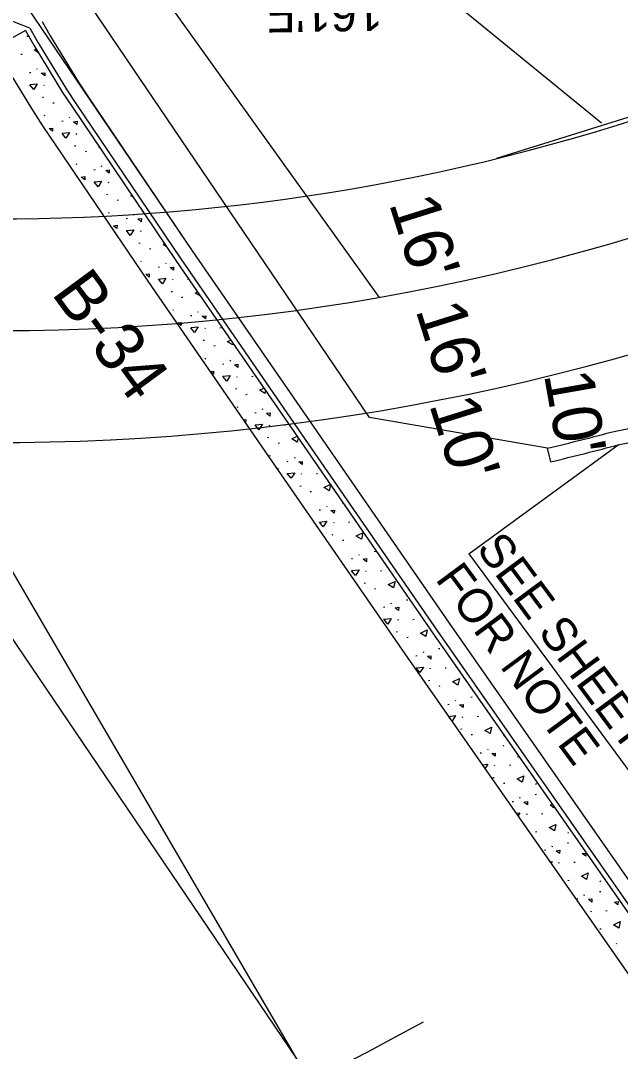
# Model space of a CAD drawing. Extents: x 1966090 to 1975830, y 788086 to 801233.
# Drawn here: x 1971355.4 to 1971441.1, y 796145.9 to 796293.3 of the extents above; entities that cross this region are included whole.
import ezdxf

# ---------------------------------------------------------------- set-up
doc = ezdxf.new("R2010")
doc.units = 0
for name, color, linetype in [('BR_PRESTRESSED BEAM', 7, 'Continuous'), ('BR_PROPOSED_DRAINAGE', 7, 'Continuous'), ('BR_REBAR', 7, 'Continuous'), ('BR_SITE LOCATION', 7, 'Continuous'), ('RD_EX_Driveway_txCode', 7, 'Continuous'), ('RD_EX_RW_TX', 7, 'Continuous'), ('RD_EX_SU_Gas', 7, 'Continuous'), ('RD_EX_TX_Dam_ELEV', 7, 'Continuous'), ('RD_PD_PaveShd', 7, 'Continuous'), ('RD_PD_RW_TX', 7, 'Continuous'), ('RD_Sketch6', 7, 'Continuous'), ('RD_Sketch8', 7, 'Continuous')]:
    doc.layers.add(name, color=color, linetype=linetype)

msp = doc.modelspace()

# ---------------------------------------------------------------- linework, layer by layer
at = {"layer": 'BR_PRESTRESSED BEAM'}
msp.add_line((1971458.75, 796284.65), (1971423.44, 796273.61), dxfattribs=at)
at = {"layer": 'BR_PROPOSED_DRAINAGE'}
msp.add_line((1971321.61, 796270.35), (1971480.17, 795998.61), dxfattribs=at)
msp.add_lwpolyline([(1971355.49, 796296.53), (1971379.93, 796260.39), (1971397.2, 796235.33), (1971416.64, 796207.13), (1971494.67, 796095.38), (1971512.27, 796070.43)], dxfattribs=at)
at = {"layer": 'BR_REBAR'}
for p, q in [((1971440.43, 796234.62), (1971528.98, 796252.31)), ((1971440.82, 796232.66), (1971518, 796248.07)), ((1971431.2, 796230.22), (1971430.74, 796232.16))]:
    msp.add_line(p, q, dxfattribs=at)
for points in [[(1971358.49, 796293.18), (1971359.61, 796291.14), (1971363.68, 796284.48), (1971364.94, 796282.55), (1971379.93, 796260.39), (1971397.2, 796235.33), (1971416.64, 796207.13), (1971494.67, 796095.38), (1971512.27, 796070.43)], [(1971356.73, 796292.22), (1971357.88, 796290.13), (1971361.99, 796283.41), (1971363.28, 796281.44), (1971378.28, 796259.26), (1971395.55, 796234.19), (1971414.99, 796205.99), (1971493.03, 796094.24), (1971510.62, 796069.31)]]:
    msp.add_lwpolyline(points, dxfattribs=at)
for radius in [340, 342]:
    msp.add_arc((1971352.19, 796562.97), radius, 283.357, 285.0421, dxfattribs=at)
at = {"layer": 'BR_SITE LOCATION'}
for p, q in [((1971356.11, 796291.89), (1971351.73, 796289.49)), ((1971356.27, 796291.07), (1971356.45, 796291.1)), ((1971355.41, 796288.49), (1971355.59, 796288.52)), ((1971357.35, 796289.09), (1971357.61, 796289.22)), ((1971357.89, 796288.76), (1971357.36, 796289.08)), ((1971356.68, 796285.87), (1971356.86, 796285.9)), ((1971357.77, 796286.42), (1971357.72, 796286.3)), ((1971358.76, 796284.08), (1971358.7, 796283.96)), ((1971358.5, 796282.34), (1971358.68, 796282.37)), ((1971360.01, 796281.54), (1971360.19, 796281.57)), ((1971361.95, 796282.14), (1971361.97, 796282.15)), ((1971361.99, 796282.12), (1971361.96, 796282.13)), ((1971358.79, 796279.76), (1971358.74, 796279.63)), ((1971362.37, 796279.47), (1971362.32, 796279.35)), ((1971361.28, 796278.92), (1971361.46, 796278.95)), ((1971363.36, 796277.14), (1971363.3, 796277.01)), ((1971363.1, 796275.39), (1971363.28, 796275.42)), ((1971366.55, 796275.2), (1971366.63, 796275.23)), ((1971366.72, 796275.09), (1971366.57, 796275.18)), ((1971364.61, 796274.59), (1971364.79, 796274.62)), ((1971363.39, 796272.81), (1971363.34, 796272.69)), ((1971365.88, 796271.97), (1971366.06, 796272)), ((1971366.97, 796272.53), (1971366.92, 796272.4)), ((1971367.96, 796270.19), (1971367.9, 796270.07)), ((1971367.7, 796268.44), (1971367.88, 796268.47)), ((1971369.21, 796267.64), (1971369.39, 796267.67)), ((1971371.15, 796268.25), (1971371.3, 796268.32)), ((1971371.49, 796268.04), (1971371.17, 796268.24)), ((1971367.99, 796265.86), (1971367.94, 796265.74)), ((1971370.48, 796265.02), (1971370.66, 796265.05)), ((1971371.57, 796265.58), (1971371.52, 796265.45)), ((1971372.56, 796263.24), (1971372.51, 796263.12)), ((1971374.67, 796263.28), (1971374.7, 796263.29)), ((1971372.3, 796261.49), (1971372.48, 796261.52)), ((1971373.81, 796260.69), (1971373.99, 796260.72)), ((1971375.75, 796261.3), (1971375.97, 796261.41)), ((1971376.26, 796260.98), (1971375.77, 796261.29)), ((1971372.59, 796258.91), (1971372.54, 796258.79)), ((1971375.08, 796258.07), (1971375.26, 796258.1)), ((1971376.17, 796258.63), (1971376.12, 796258.51)), ((1971377.16, 796256.29), (1971377.11, 796256.17)), ((1971379.27, 796256.33), (1971379.42, 796256.36)), ((1971376.91, 796254.55), (1971377.09, 796254.58)), ((1971380.35, 796254.35), (1971380.69, 796254.51)), ((1971378.41, 796253.74), (1971378.59, 796253.77)), ((1971377.2, 796251.96), (1971377.14, 796251.84)), ((1971380.77, 796251.68), (1971380.72, 796251.56)), ((1971379.68, 796251.12), (1971379.86, 796251.15)), ((1971381.76, 796249.34), (1971381.71, 796249.22)), ((1971383.87, 796249.38), (1971384.05, 796249.41)), ((1971381.51, 796247.6), (1971381.69, 796247.63)), ((1971384.95, 796247.4), (1971385.43, 796247.63)), ((1971383.01, 796246.8), (1971383.19, 796246.83)), ((1971381.8, 796245.02), (1971381.74, 796244.89)), ((1971384.28, 796244.18), (1971384.46, 796244.21)), ((1971385.38, 796244.73), (1971385.32, 796244.61)), ((1971386.36, 796242.39), (1971386.31, 796242.27)), ((1971388.47, 796242.44), (1971388.65, 796242.47)), ((1971386.11, 796240.65), (1971386.29, 796240.68)), ((1971387.61, 796239.85), (1971387.79, 796239.88)), ((1971389.55, 796240.45), (1971390.18, 796240.75)), ((1971386.4, 796238.07), (1971386.34, 796237.94)), ((1971388.88, 796237.23), (1971389.06, 796237.26)), ((1971389.98, 796237.78), (1971389.92, 796237.66)), ((1971390.96, 796235.45), (1971390.91, 796235.32)), ((1971393.07, 796235.49), (1971393.25, 796235.52)), ((1971390.71, 796233.7), (1971390.89, 796233.73)), ((1971394.15, 796233.51), (1971394.92, 796233.87)), ((1971392.21, 796232.9), (1971392.39, 796232.93)), ((1971391, 796231.12), (1971390.95, 796231)), ((1971394.58, 796230.84), (1971394.53, 796230.71)), ((1971393.48, 796230.28), (1971393.66, 796230.31)), ((1971395.56, 796228.5), (1971395.51, 796228.38)), ((1971397.67, 796228.54), (1971397.85, 796228.57)), ((1971395.31, 796226.75), (1971395.49, 796226.78)), ((1971398.76, 796226.56), (1971399.66, 796226.99)), ((1971396.81, 796225.95), (1971396.99, 796225.98)), ((1971395.6, 796224.17), (1971395.57, 796224.11)), ((1971398.08, 796223.33), (1971398.26, 796223.36)), ((1971399.18, 796223.89), (1971399.13, 796223.76)), ((1971401.35, 796224.35), (1971401.46, 796224.37)), ((1971400.16, 796221.55), (1971400.11, 796221.43)), ((1971402.27, 796221.59), (1971402.45, 796221.62)), ((1971399.91, 796219.8), (1971400.09, 796219.83)), ((1971401.41, 796219), (1971401.59, 796219.03)), ((1971405.95, 796217.41), (1971406.13, 796217.44)), ((1971402.68, 796216.38), (1971402.86, 796216.41)), ((1971403.78, 796216.94), (1971403.73, 796216.82)), ((1971404.76, 796214.6), (1971404.71, 796214.48)), ((1971406.87, 796214.64), (1971407.05, 796214.67)), ((1971404.51, 796212.86), (1971404.69, 796212.89)), ((1971406.01, 796212.05), (1971406.19, 796212.08)), ((1971410.55, 796210.46), (1971410.73, 796210.49)), ((1971407.28, 796209.44), (1971407.46, 796209.47)), ((1971408.38, 796209.99), (1971408.33, 796209.87)), ((1971409.36, 796207.65), (1971409.31, 796207.53)), ((1971411.47, 796207.69), (1971411.65, 796207.72)), ((1971409.11, 796205.91), (1971409.29, 796205.94)), ((1971410.61, 796205.11), (1971410.79, 796205.14)), ((1971412.98, 796203.04), (1971412.93, 796202.92)), ((1971415.15, 796203.51), (1971415.33, 796203.54)), ((1971411.89, 796202.49), (1971412.07, 796202.52)), ((1971413.96, 796200.71), (1971413.91, 796200.58)), ((1971416.07, 796200.75), (1971416.25, 796200.78)), ((1971413.71, 796198.96), (1971413.89, 796198.99)), ((1971415.21, 796198.16), (1971415.39, 796198.19)), ((1971416.49, 796195.54), (1971416.67, 796195.57)), ((1971417.58, 796196.09), (1971417.53, 796195.97)), ((1971419.76, 796196.56), (1971419.93, 796196.59)), ((1971418.56, 796193.76), (1971418.51, 796193.63)), ((1971420.68, 796193.8), (1971420.85, 796193.83)), ((1971418.31, 796192.01), (1971418.49, 796192.04)), ((1971419.82, 796191.21), (1971420, 796191.24)), ((1971424.52, 796191.11), (1971424.41, 796191.01)), ((1971424.36, 796189.61), (1971424.54, 796189.64)), ((1971421.09, 796188.59), (1971421.27, 796188.62)), ((1971422.18, 796189.15), (1971422.13, 796189.02)), ((1971426.5, 796188.1), (1971426.61, 796188.12)), ((1971426.79, 796187.87), (1971426.5, 796188.1)), ((1971423.16, 796186.81), (1971423.11, 796186.69)), ((1971425.28, 796186.85), (1971425.46, 796186.88)), ((1971422.91, 796185.06), (1971423.09, 796185.09)), ((1971424.42, 796184.26), (1971424.6, 796184.29)), ((1971429.14, 796184.17), (1971429.01, 796184.06)), ((1971426.78, 796182.2), (1971426.73, 796182.07)), ((1971428.96, 796182.66), (1971429.14, 796182.7)), ((1971425.69, 796181.64), (1971425.87, 796181.67)), ((1971431.1, 796181.15), (1971431.44, 796181.2)), ((1971427.76, 796179.86), (1971427.71, 796179.74)), ((1971429.88, 796179.9), (1971430.06, 796179.93)), ((1971427.51, 796178.11), (1971427.69, 796178.14)), ((1971429.02, 796177.31), (1971429.2, 796177.34)), ((1971433.74, 796177.22), (1971433.61, 796177.11)), ((1971430.29, 796174.69), (1971430.47, 796174.72)), ((1971431.38, 796175.25), (1971431.33, 796175.13)), ((1971433.56, 796175.72), (1971433.74, 796175.75)), ((1971432.36, 796172.91), (1971432.31, 796172.79)), ((1971434.48, 796172.95), (1971434.66, 796172.98)), ((1971433.62, 796170.36), (1971433.8, 796170.4)), ((1971438.34, 796170.27), (1971438.21, 796170.16)), ((1971438.16, 796168.77), (1971438.34, 796168.8)), ((1971434.89, 796167.75), (1971435.07, 796167.78)), ((1971435.98, 796168.3), (1971435.93, 796168.18)), ((1971436.97, 796165.96), (1971436.91, 796165.84)), ((1971439.08, 796166.01), (1971439.26, 796166.04)), ((1971438.22, 796163.42), (1971438.4, 796163.45)), ((1971439.58, 796160.81), (1971439.67, 796160.83)), ((1971440.58, 796161.35), (1971440.53, 796161.23))]:
    msp.add_line(p, q, dxfattribs=at)
for points in [[(1971356.11, 796291.89), (1971357.26, 796289.78), (1971361.39, 796283.03), (1971362.69, 796281.05), (1971377.69, 796258.87), (1971394.97, 796233.79), (1971414.41, 796205.59), (1971492.45, 796093.83), (1971517.1, 796058.89)], [(1971351.73, 796289.49), (1971352.93, 796287.27), (1971357.17, 796280.35), (1971358.53, 796278.28), (1971373.56, 796256.05), (1971390.85, 796230.96), (1971410.3, 796202.74), (1971488.36, 796090.96), (1971513.02, 796056.01)], [(1971358.35, 796285.79), (1971358.86, 796285.86), (1971358.83, 796285.39), (1971358.35, 796285.79)], [(1971356.71, 796284.15), (1971357.77, 796284.25), (1971357.26, 796283.45), (1971356.72, 796284.13)], [(1971359.46, 796277.87), (1971359.97, 796277.94), (1971359.94, 796277.48), (1971359.46, 796277.87)], [(1971362.95, 796278.84), (1971363.46, 796278.91), (1971363.43, 796278.45), (1971362.95, 796278.84)], [(1971361.31, 796277.2), (1971362.37, 796277.3), (1971361.86, 796276.5), (1971361.32, 796277.18)], [(1971364.06, 796270.92), (1971364.57, 796270.99), (1971364.55, 796270.53), (1971364.06, 796270.92)], [(1971367.55, 796271.89), (1971368.06, 796271.96), (1971368.03, 796271.5), (1971367.55, 796271.89)], [(1971365.91, 796270.25), (1971366.97, 796270.35), (1971366.46, 796269.55), (1971365.92, 796270.23)], [(1971372.15, 796264.94), (1971372.66, 796265.01), (1971372.63, 796264.55), (1971372.15, 796264.94)], [(1971368.67, 796263.98), (1971369.17, 796264.05), (1971369.15, 796263.58), (1971368.67, 796263.98)], [(1971370.51, 796263.3), (1971371.57, 796263.41), (1971371.06, 796262.6), (1971370.52, 796263.29)], [(1971376.75, 796257.99), (1971377.26, 796258.06), (1971377.23, 796257.6), (1971376.75, 796257.99)], [(1971373.27, 796257.03), (1971373.77, 796257.1), (1971373.75, 796256.64), (1971373.27, 796257.03)], [(1971375.11, 796256.35), (1971376.17, 796256.46), (1971375.66, 796255.65), (1971375.12, 796256.34)], [(1971381.11, 796253.9), (1971381.11, 796253.88), (1971380.37, 796254.34)], [(1971377.87, 796250.08), (1971378.37, 796250.15), (1971378.35, 796249.69), (1971377.87, 796250.08)], [(1971381.35, 796251.04), (1971381.86, 796251.11), (1971381.83, 796250.65), (1971381.35, 796251.04)], [(1971379.71, 796249.4), (1971380.77, 796249.51), (1971380.26, 796248.7), (1971379.72, 796249.39)], [(1971385.76, 796247.16), (1971385.71, 796246.93), (1971384.97, 796247.39)], [(1971385.95, 796244.1), (1971386.46, 796244.17), (1971386.43, 796243.7), (1971385.95, 796244.1)], [(1971382.47, 796243.13), (1971382.98, 796243.2), (1971382.95, 796242.74), (1971382.47, 796243.13)], [(1971384.31, 796242.46), (1971385.37, 796242.56), (1971384.86, 796241.76), (1971384.32, 796242.44)], [(1971390.41, 796240.42), (1971390.31, 796239.99), (1971389.57, 796240.44)], [(1971390.55, 796237.15), (1971391.06, 796237.22), (1971391.03, 796236.76), (1971390.55, 796237.15)], [(1971387.24, 796236.21), (1971387.58, 796236.25), (1971387.55, 796235.79), (1971387.49, 796235.84)], [(1971388.91, 796235.51), (1971389.97, 796235.61), (1971389.46, 796234.81), (1971388.92, 796235.49)], [(1971395.05, 796233.68), (1971394.91, 796233.04), (1971394.17, 796233.49)], [(1971392.01, 796229.28), (1971392.18, 796229.3), (1971392.16, 796229.06)], [(1971395.15, 796230.2), (1971395.66, 796230.27), (1971395.63, 796229.81), (1971395.15, 796230.2)], [(1971393.51, 796228.56), (1971394.58, 796228.66), (1971394.06, 796227.86), (1971393.52, 796228.54)], [(1971399.7, 796226.93), (1971399.51, 796226.09), (1971398.77, 796226.55)], [(1971399.75, 796223.25), (1971400.26, 796223.32), (1971400.23, 796222.86), (1971399.75, 796223.25)], [(1971398.11, 796221.61), (1971399.18, 796221.72), (1971398.67, 796220.91), (1971398.12, 796221.6)], [(1971403.36, 796219.61), (1971404.32, 796220.07), (1971404.11, 796219.14), (1971403.37, 796219.6)], [(1971404.35, 796216.3), (1971404.86, 796216.37), (1971404.84, 796215.91), (1971404.35, 796216.3)], [(1971402.71, 796214.66), (1971403.78, 796214.77), (1971403.27, 796213.96), (1971402.72, 796214.65)], [(1971407.96, 796212.66), (1971408.92, 796213.12), (1971408.71, 796212.19), (1971407.97, 796212.65)], [(1971408.95, 796209.35), (1971409.46, 796209.43), (1971409.44, 796208.96), (1971408.95, 796209.35)], [(1971407.31, 796207.71), (1971408.38, 796207.82), (1971407.87, 796207.01), (1971407.32, 796207.7)], [(1971412.56, 796205.71), (1971413.52, 796206.17), (1971413.31, 796205.24), (1971412.57, 796205.7)], [(1971413.56, 796202.41), (1971414.06, 796202.48), (1971414.04, 796202.02), (1971413.56, 796202.41)], [(1971411.92, 796200.77), (1971412.98, 796200.87), (1971412.47, 796200.07), (1971411.93, 796200.75)], [(1971417.16, 796198.76), (1971418.12, 796199.23), (1971417.92, 796198.3), (1971417.17, 796198.75)], [(1971418.16, 796195.46), (1971418.66, 796195.53), (1971418.64, 796195.07), (1971418.16, 796195.46)], [(1971416.53, 796193.82), (1971417.58, 796193.92), (1971417.07, 796193.12), (1971416.68, 796193.61)], [(1971421.76, 796191.82), (1971422.72, 796192.28), (1971422.52, 796191.35), (1971421.77, 796191.8)], [(1971422.76, 796188.51), (1971423.26, 796188.58), (1971423.24, 796188.12), (1971422.76, 796188.51)], [(1971421.37, 796186.89), (1971422.18, 796186.97), (1971421.77, 796186.32)], [(1971426.36, 796184.87), (1971427.32, 796185.33), (1971427.12, 796184.4), (1971426.37, 796184.86)], [(1971427.36, 796181.56), (1971427.87, 796181.63), (1971427.84, 796181.17), (1971427.36, 796181.56)], [(1971431.6, 796180.98), (1971431.58, 796180.76), (1971431.1, 796181.15)], [(1971426.2, 796179.97), (1971426.78, 796180.03), (1971426.49, 796179.56)], [(1971430.96, 796177.92), (1971431.92, 796178.38), (1971431.72, 796177.45), (1971430.97, 796177.91)], [(1971431.96, 796174.61), (1971432.47, 796174.68), (1971432.44, 796174.22), (1971431.96, 796174.61)], [(1971435.7, 796174.2), (1971436.21, 796174.27), (1971436.18, 796173.81), (1971435.7, 796174.2)], [(1971431.04, 796173.04), (1971431.38, 796173.08), (1971431.21, 796172.8)], [(1971435.56, 796170.97), (1971436.52, 796171.43), (1971436.32, 796170.5), (1971435.57, 796170.96)], [(1971436.56, 796167.67), (1971437.07, 796167.74), (1971437.04, 796167.27), (1971436.56, 796167.67)], [(1971440.3, 796167.26), (1971440.81, 796167.33), (1971440.78, 796166.86), (1971440.3, 796167.26)], [(1971435.87, 796166.12), (1971435.98, 796166.13), (1971435.93, 796166.04)], [(1971440.16, 796164.02), (1971441.12, 796164.48), (1971440.92, 796163.55), (1971440.18, 796164.01)]]:
    msp.add_lwpolyline(points, dxfattribs=at)
at = {"layer": 'RD_EX_SU_Gas'}
msp.add_arc((1971051.22, 796804.85), 780, 298.92325, 306.04973, dxfattribs=at)
at = {"layer": 'RD_EX_TX_Dam_ELEV'}
msp.add_line((1971430.74, 796232.16), (1971405.27, 796236.53), dxfattribs=at)
for points in [[(1971405.27, 796236.53), (1971364.41, 796296.88)], [(1971469.8, 796034.17), (1971314.72, 796263.25)]]:
    msp.add_lwpolyline(points, dxfattribs=at)
at = {"layer": 'RD_PD_PaveShd'}
msp.add_arc((1971210.82, 796516.01), 418, 222.4751, 298.9233, dxfattribs=at)
at = {"layer": 'RD_PD_RW_TX'}
msp.add_arc((1971352.19, 796562.97), 298, 221.212, 301.3407, dxfattribs=at)
at = {"layer": 'RD_Sketch6'}
for p, q in [((1971376.99, 796328.91), (1971438.42, 796278.68)), ((1971356.87, 796323.19), (1971406.64, 796253.73)), ((1971356.73, 796292.22), (1971325.67, 796304.26)), ((1971419.46, 796217.05), (1971440.82, 796232.66))]:
    msp.add_line(p, q, dxfattribs=at)
msp.add_lwpolyline([(1971419.46, 796217.05), (1971447.43, 796179.11), (1971476.51, 796191.95)], dxfattribs=at)
at = {"layer": 'RD_Sketch8'}
for centre, radius, start, end in [((1971352.19, 796562.97), 314, 221.212, 318.863), ((1971352.19, 796562.97), 330, 221.212, 316.8104), ((1971210.82, 796516.01), 438, 216.3977, 298.9233), ((1971051.22, 796804.85), 768, 298.92325, 314.33883), ((1971051.22, 796804.85), 792, 298.92325, 312.19164)]:
    msp.add_arc(centre, radius, start, end, dxfattribs=at)

# ---------------------------------------------------------------- texts
at = {"layer": 'RD_EX_Driveway_txCode'}
for s, rotation, p in [("16'", 287.4859, (1971408.02, 796267.18)), ('B-34', 306.3976, (1971359.67, 796254.31)), ("16'", 287.4859, (1971411.81, 796251.96)), ("10'", 279.987, (1971430.19, 796242.73)), ("10'", 287.4859, (1971413.76, 796238.44))]:
    msp.add_text(s, height=7, rotation=rotation, dxfattribs=at).set_placement(p)
at = {"layer": 'RD_EX_RW_TX'}
msp.add_text("161'F", height=5, rotation=180.9669, dxfattribs=at).set_placement((1971407.11, 796296.87))
at = {"layer": 'RD_Sketch6'}
for s, height, p in [('SEE SHEET 22', 4.8596, (1971420.43, 796217.77)), ('FOR NOTE', 4.86, (1971414.58, 796213.43))]:
    msp.add_text(s, height=height, rotation=306.5574, dxfattribs=at).set_placement(p)

doc.saveas('drawing.dxf')
